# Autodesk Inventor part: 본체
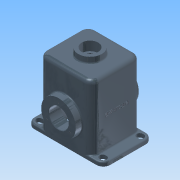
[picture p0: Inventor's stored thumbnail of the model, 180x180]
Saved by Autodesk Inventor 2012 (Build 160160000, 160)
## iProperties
Company: 한국ATC센터
Created: 2014-10
Part Number: 본체
Document SubType Name: Modeling
Designer: 한국ATC센터
Density: 2.71 g/cm^3
Material: 알루미늄-6061
Mass: 3285.44 g
Surface Area: 2358.47 cm^2
Volume: 1212.34 cm^3
Author: KYOUNG IL JANG
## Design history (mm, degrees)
sketch "스케치1"
  geometry: L1 (-70, 65)-(70, 65); L2 (70, 65)-(70, -65); L3 (70, -65)-(-70, -65); L4 (-70, -65)-(-70, 65); 3 further points
  constraints: 8 end point, 2 midpoint, 2 parallel, 1 horizontal, 1 horizontal alignment, 1 perpendicular, 1 vertical alignment
  dimensions: "d0" = 140 distance of L2.end L3.end; "d68" = 130 distance of L3.end L1.start
extrude "돌출1" new body sketch "스케치1" distance "d1" = 180; taper "d2" = 0 deg
fillet "모깎기1" dims "d3" = 20
feature "쉘1" dims "d4" = 10
sketch "스케치2"
  geometry: L1 (-70, 45)-(-70, -45) reference; L2 (-50, -65)-(-82, -65); L3 (-82, 65)-(-50, 65); L4 (-85, 57)-(-82, 57); L5 (-82, 41)-(-85, 41); L6 (-100, 47)-(-100, -47); A1 r 20 centre (-50, 45) between (-50, 65) and (-70, 45) reference; A2 r 20 centre (-50, -45) between (-70, -45) and (-50, -65) reference; A3 r 8 centre (-82, 49) between (-82, 41) and (-82, 57); A4 r 8 centre (-85, 49) between (-85, 57) and (-85, 41); A5 r 18 centre (-82, 47) between (-82, 65) and (-100, 47); A6 r 18 centre (-82, -47) between (-100, -47) and (-82, -65); 1 further point
  constraints: 10 end point, 9 tangent, 8 point on circle, 4 centre point, 2 parallel, 2 perpendicular, 1 equal radius
  dimensions: "d6" = 49 vertical distance of point (0, 0) A3.centre; "d8" = 16 distance between parallel lines of L4 L5; "d64" = 18 radius of A5; "d65" = 12 distance from line of A3.centre L1; "d66" = 30 distance between parallel lines of L6 L1; "d67" = 3 distance of A4.centre A3.centre
extrude "돌출2" join sketch "스케치2" distance "d9" = 10; taper "d10" = 0 deg
extrude "돌출3" cut sketch "스케치2" stored distance "d11" = 10; taper "d12" = 0 deg
sketch "스케치3"
  geometry: L1 (-65, 0)-(-65, 180) reference; L2 (-55, 0)-(-55, 170) reference; L3 (-83, 75)-(-51, 75); L4 (45, 0)-(-45, 0) reference; L5 (-83, 75)-(-83, 120.5); L6 (-83, 120.5)-(-55, 120.5); L7 (-55, 120.5)-(-51, 116.5); L8 (-51, 116.5)-(-51, 75); 2 further points
  constraints: 10 end point, 4 perpendicular, 1 point on line
  dimensions: "d13" = 75 distance between parallel lines of L3 L4; "d14" = 18 distance from line of L1 L3.start; "d15" = 4 distance from line of L3.end L2; "d16" = 91 diameter of L6 L3; "d17" = 135 deg angle of L7 L2
revolve "회전1" sketch "스케치3" stored, may be unused: angle "d18" = 90 deg
sketch "스케치4"
  geometry: C1 r 45.5 at (0, 0) reference; 2 further points
  constraints: 1 vertical alignment
  dimensions: "d19" = 35 distance of C1.centre point (0, 35)
hole "구멍1" sketch "스케치4" at (0, 35) diameter "d20" = 3.459; stored, may be unused: countersink angle "d24" = 90 deg, drill point angle "d26" = 118 deg; dims "d21" = 13, "d22" = 4, "d23" = 2, "d25" = 16
fillet "모깎기2" dims "d30" = 3
hole "구멍2" diameter "d33" = 52; stored, may be unused: countersink angle "d37" = 90 deg, drill point angle "d39" = 118 deg; dims "d31" = 10, "d32" = 10, "d34" = 13, "d35" = 4, "d36" = 2, "d38" = 16
sketch "스케치5"
  geometry: C1 r 31 at (0, 0); 1 further point
  constraints: 1 centre point, 1 coincident
  dimensions: "d40" = 62 diameter of C1
extrude "돌출4" join sketch "스케치5" distance "d41" = 15; taper "d42" = 0 deg
hole "구멍3" diameter "d45" = 43; stored, may be unused: countersink angle "d49" = 90 deg, drill point angle "d51" = 118 deg; dims "d43" = 10, "d44" = 10, "d46" = 13, "d47" = 4, "d48" = 2, "d50" = 16
fillet "모깎기3" dims "d52" = 3
fillet "모깎기4" dims "d53" = 3
chamfer "모따기1" distance "d55" = 1; stored, may be unused: second distance "d56" = 2, angle "d57" = 45 deg
sketch "스케치6"
  geometry: 2 further points
  constraints: 1 vertical alignment, 1 other
  dimensions: "d71" = 90 distance of point (0, 0) point (0, 90)
feature "엠보싱2" sketch "스케치6" dims "d0" = 140, "d68" = 130, "d72" = 1, "d73" = 0
fillet "모깎기6" dims "d74" = 10
sketch "스케치7"
  geometry: C1 r 15 at (0, 0); C2 r 21.5 at (0, 0) reference; C3 r 25 at (0, 0); 1 further point
  constraints: 2 centre point, 2 coincident
  dimensions: "d61" = 30 diameter of C1; "d75" = 50 diameter of C3
extrude "돌출5" join sketch "스케치7" distance "d62" = 10; taper "d63" = 0 deg
feature "면 이동1" dims "d76" = 1
fillet "모깎기7" dims "d77" = 3
node "솔리드1"
mirror "대칭1"
mirror "대칭2"
pattern_circular "원형 패턴1" dims angle "d28" = 360 deg
mirror "대칭3"
